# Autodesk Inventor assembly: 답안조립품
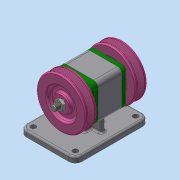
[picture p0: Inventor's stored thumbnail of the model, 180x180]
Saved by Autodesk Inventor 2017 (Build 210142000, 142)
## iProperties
Part Number: 답안조립품
Material: 일반
Document SubType Name: Assembly
Designer: 7-1
Author: 7-1
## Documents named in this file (10)
- C:\Users\7-1\Desktop\701106V1054\답안조립품.iam
- C:\Users\7-1\Desktop\701106V1054\본체.ipt
- C:\Users\7-1\Desktop\701106V1054\축.ipt
- C:\Users\7-1\Desktop\701106V1054\베어링 6004.ipt
- C:\Users\7-1\Desktop\701106V1054\Ű 5 x 5 x 12.ipt
- C:\Users\7-1\Desktop\701106V1054\커버.ipt
- C:\Users\7-1\Desktop\701106V1054\오일 실 17 30 5.ipt
- C:\Users\7-1\Desktop\701106V1054\볼트 M4.ipt
- C:\Users\7-1\Desktop\701106V1054\V-벨트풀리.ipt
- C:\Users\7-1\Desktop\701106V1054\너트 M10x1.ipt
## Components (4 placed, 2 different names)
1. Ű 5 x 5 x 12:1
2. Ű 5 x 5 x 12:2
3. V-벨트풀리:1
4. V-벨트풀리:2
